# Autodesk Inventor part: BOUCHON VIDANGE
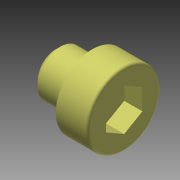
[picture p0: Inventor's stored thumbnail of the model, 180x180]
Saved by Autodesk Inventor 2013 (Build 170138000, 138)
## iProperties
Created: 2012-12
Part Number: BOUCHON VIDANGE
Material: Générique
Document SubType Name: Modeling
Designer: jost thierry
Density: 1 g/cm^3
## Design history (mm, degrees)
node "BOUCHON VIDANGE1"
node "BOUCHON VIDANGE"
node "Base1"
